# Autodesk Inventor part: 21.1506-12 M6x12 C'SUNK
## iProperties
Created: 2006-12
Part Number: 21.1506-12 M6x12 C'SUNK
Material: Steel, Mild
Description: Hexagon socket countersunk head cap screws
Document SubType Name: Modeling
Standard: DIN 7991
Designer: Andy Moles
Standards Organization: DIN
Language: en-US
Size Designation: M6x16
Categories: <MemberInstance Version="R10.0.0"><Categories><Category DisplayName="Fasteners" InternalName="e4da775c-781d-43d5-af7c-5136215cf5a6" Mnemonic="FSTN"><Category Di
Density: 7.86 g/cm^3
Mass: 3.46631 g
Surface Area: 4.65192 cm^2
Volume: 0.441007 cm^3
Author: Andy Moles
Revision Number: 1
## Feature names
1. Revolution1
2. Extrusion1
3. Fillet1
4. Chamfer1
